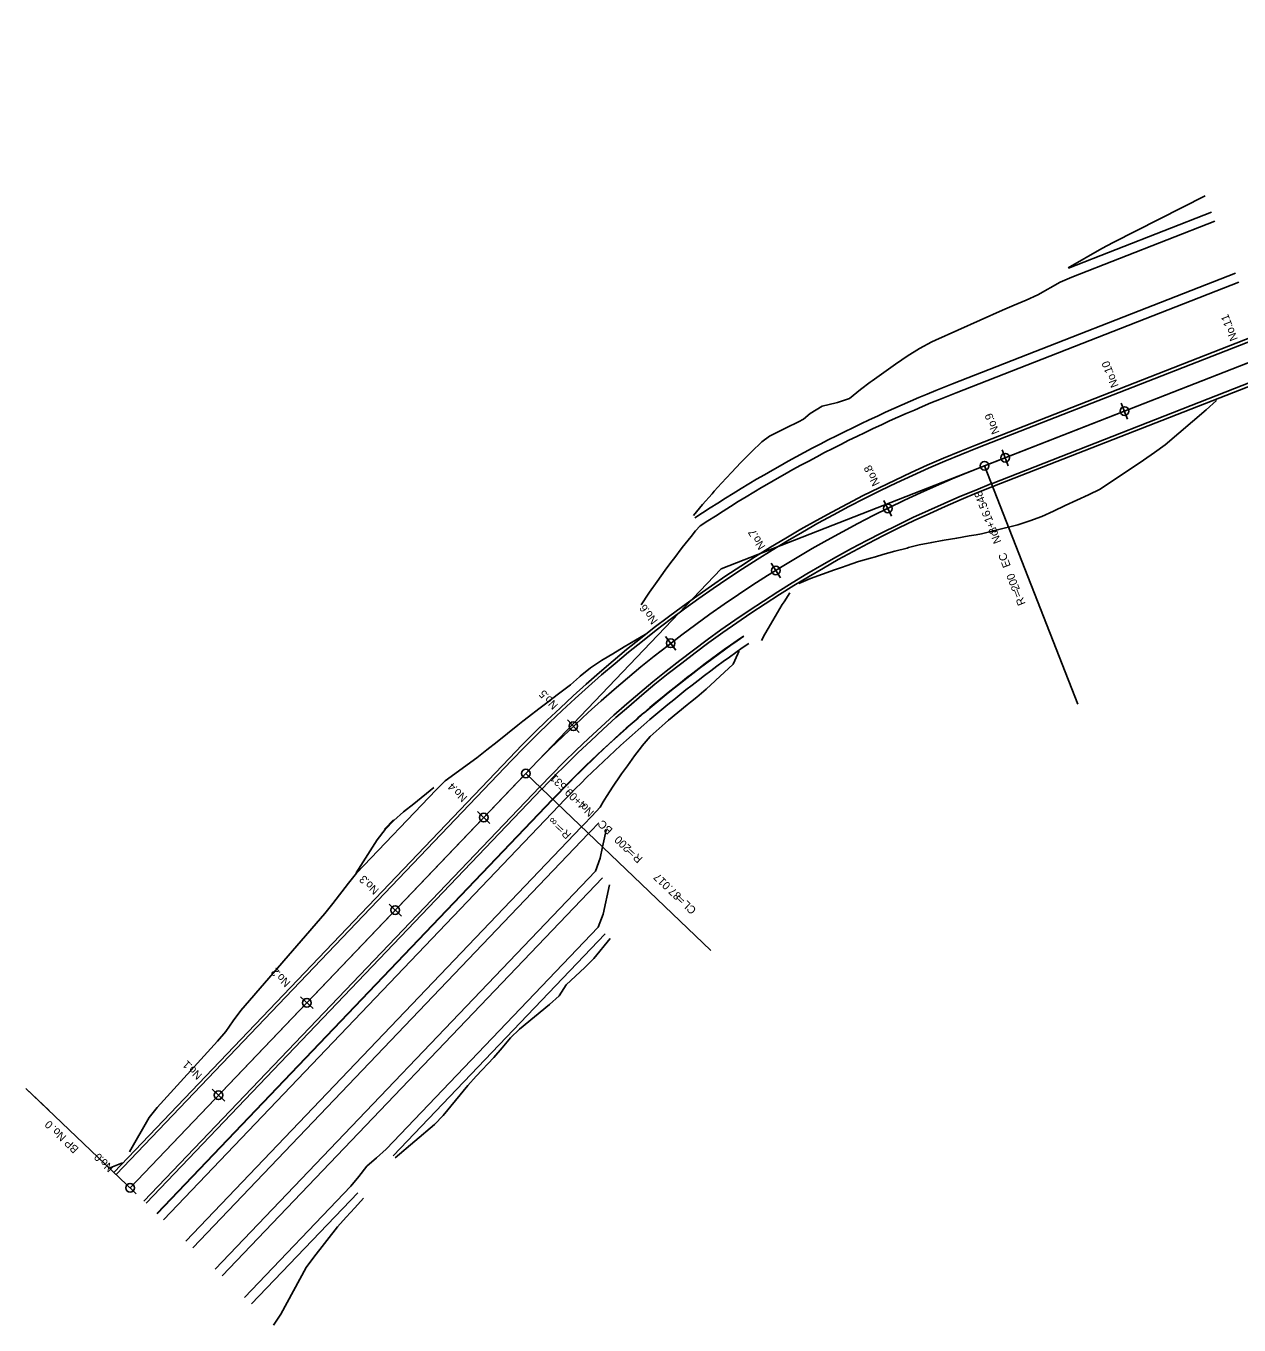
# Model space of a CAD drawing. Extents: x 46571 to 46965, y 10701 to 11034.
# Drawn here: x 46571.1 to 46760.7, y 10701.1 to 10904 of the extents above; entities that cross this region are included whole.
import ezdxf

# ---------------------------------------------------------------- set-up
doc = ezdxf.new("R2010")
doc.units = 0
for name, color, linetype in [('Default', 7, 'Continuous'), ('作業レイヤ1', 7, 'Continuous'), ('地形_土崖 コンクリート、堅固な石積等斜面（地理院地図Vector）', 7, 'Continuous'), ('建物_堅ろう建物_堅ろう建物（外周線）（地理院地図Vector）', 7, 'Continuous'), ('建物_普通建物_普通建物（外周線）（地理院地図Vector）', 7, 'Continuous'), ('河川_通常部（地理院地図Vector）', 7, 'Continuous'), ('現況_地形', 7, 'Continuous'), ('現況_地形_フロー矢印', 7, 'Continuous'), ('現況_地形_単点標高', 7, 'Continuous'), ('等高線等深線_等高線_主曲線通常部（地理院地図Vector）', 7, 'Continuous'), ('道路_通常部_通常部（地理院地図Vector）', 7, 'Continuous')]:
    doc.layers.add(name, color=color, linetype=linetype)

msp = doc.modelspace()

# ---------------------------------------------------------------- linework, layer by layer
at = {"layer": 'Default'}
for p, q in [((46679.76, 10819.21), (46896.47, 10904.04)), ((46720.93, 10835.33), (46842.51, 10882.92)), ((46742.77, 10843.88), (46742.77, 10843.88)), ((46724.14, 10836.59), (46724.14, 10836.59)), ((46720.93, 10835.33), (46720.93, 10835.33)), ((46720.93, 10835.33), (46735.51, 10798.08)), ((46705.79, 10828.67), (46705.79, 10828.67)), ((46587.37, 10722.52), (46679.76, 10819.21)), ((46688.3, 10818.98), (46688.3, 10818.98)), ((46671.86, 10807.59), (46671.86, 10807.59)), ((46656.65, 10794.63), (46656.65, 10794.63)), ((46587.37, 10722.52), (46649.22, 10787.25)), ((46649.22, 10787.25), (46649.22, 10787.25)), ((46649.22, 10787.25), (46678.14, 10759.62)), ((46642.64, 10780.36), (46642.64, 10780.36)), ((46628.82, 10765.9), (46628.82, 10765.9)), ((46615, 10751.44), (46615, 10751.44)), ((46586.88, 10722.98), (46571.1, 10738.06)), ((46571.1, 10738.06), (46574.72, 10734.61)), ((46601.19, 10736.98), (46601.19, 10736.98)), ((46587.37, 10722.52), (46587.37, 10722.52)), ((46587.37, 10722.52), (46587.37, 10722.52))]:
    msp.add_line(p, q, dxfattribs=at)
for centre in [(46742.77, 10843.88), (46720.93, 10835.33), (46724.14, 10836.59), (46705.79, 10828.67), (46688.3, 10818.98), (46671.86, 10807.59), (46656.65, 10794.63), (46649.22, 10787.25), (46642.64, 10780.36), (46628.82, 10765.9), (46615, 10751.44), (46601.19, 10736.98), (46587.37, 10722.52), (46587.37, 10722.52)]:
    msp.add_circle(centre, 0.675, dxfattribs=at)
msp.add_arc((46793.83, 10649.09), 200, 111.3768, 136.3054, dxfattribs=at)
msp.add_arc((46793.83, 10649.09), 200, 111.3768, 136.3054, dxfattribs=at)
at = {"layer": '作業レイヤ1'}
for p, q in [((46720.93, 10835.33), (46842.51, 10882.92)), ((46587.37, 10722.52), (46649.22, 10787.25))]:
    msp.add_line(p, q, dxfattribs=at)
msp.add_arc((46793.83, 10649.09), 200, 111.3768, 136.3054, dxfattribs=at)
at = {"layer": '地形_土崖 コンクリート、堅固な石積等斜面（地理院地図Vector）'}
for p, q in [((46719.83, 10838.12), (46841.42, 10885.71)), ((46722.02, 10832.53), (46843.6, 10880.12)), ((46585.2, 10724.59), (46647.05, 10789.32)), ((46589.54, 10720.44), (46651.39, 10785.18))]:
    msp.add_line(p, q, dxfattribs=at)
for radius in [203, 197]:
    msp.add_arc((46793.83, 10649.09), radius, 111.3768, 136.3054, dxfattribs=at)
at = {"layer": '建物_堅ろう建物_堅ろう建物（外周線）（地理院地図Vector）'}
msp.add_line((46591.57, 10718.51), (46653.41, 10783.24), dxfattribs=at)
msp.add_arc((46793.83, 10649.09), 194.2, 124.7118, 136.3054, dxfattribs=at)
at = {"layer": '建物_普通建物_普通建物（外周線）（地理院地図Vector）'}
for p, q in [((46719.65, 10838.59), (46841.23, 10886.18)), ((46722.2, 10832.07), (46843.78, 10879.66)), ((46584.84, 10724.93), (46646.69, 10789.67)), ((46589.9, 10720.1), (46651.75, 10784.83)), ((46592.59, 10717.53), (46654.44, 10782.26))]:
    msp.add_line(p, q, dxfattribs=at)
for radius, start in [(203.5, 111.3768), (196.5, 111.3768), (192.78, 124.7118)]:
    msp.add_arc((46793.83, 10649.09), radius, start, 136.3054, dxfattribs=at)
at = {"layer": '現況_地形'}
msp.add_line((46591.6, 10718.48), (46653.45, 10783.21), dxfattribs=at)
msp.add_arc((46793.83, 10649.09), 194.15, 124.7118, 136.3054, dxfattribs=at)
at = {"layer": '現況_地形_フロー矢印'}
for p, q in [((46734.03, 10866.19), (46756.38, 10874.94)), ((46715.92, 10848.11), (46760.11, 10865.41)), ((46716.47, 10846.72), (46760.66, 10864.01)), ((46584.13, 10725.61), (46586.2, 10726.4))]:
    msp.add_line(p, q, dxfattribs=at)
for points in [[(46734, 10866.27), (46739.26, 10869.29), (46741.04, 10870.23), (46755.38, 10877.49)], [(46675.41, 10827.55), (46676.85, 10829.26), (46678.32, 10830.95), (46678.68, 10831.35), (46679.82, 10832.62), (46681.35, 10834.27), (46682.83, 10835.83), (46682.9, 10835.9), (46684.48, 10837.51), (46686.09, 10839.09), (46687.31, 10839.93), (46687.94, 10840.26), (46689.89, 10841.24), (46691.86, 10842.19), (46692.62, 10842.6), (46693.64, 10843.5), (46695.52, 10844.63), (46697.7, 10845.15), (46697.95, 10845.21), (46699.79, 10845.86), (46701.53, 10847.27), (46703.03, 10848.38), (46703.33, 10848.6), (46705.15, 10849.9), (46706.99, 10851.19), (46708.01, 10851.9), (46708.84, 10852.46), (46710.73, 10853.65), (46712.7, 10854.69), (46713.25, 10854.95), (46723.72, 10859.62), (46725.55, 10860.42), (46727.4, 10861.18), (46729.22, 10862.02), (46732.73, 10864.03), (46734.58, 10864.79), (46756.93, 10873.54)], [(46691.87, 10816.95), (46693.7, 10817.71), (46695.57, 10818.4), (46697.44, 10819.07), (46698.71, 10819.51), (46699.31, 10819.72), (46701.19, 10820.36), (46703.1, 10820.91), (46703.86, 10821.12), (46705.01, 10821.44), (46706.91, 10821.97), (46708.82, 10822.48), (46709.04, 10822.54), (46710.72, 10822.99), (46712.67, 10823.36), (46714.3, 10823.65), (46714.62, 10823.71), (46716.57, 10824.04), (46718.51, 10824.36), (46719.59, 10824.54), (46720.43, 10824.71), (46722.3, 10825.17), (46724.17, 10825.62), (46724.68, 10825.75), (46726.1, 10826.09), (46728, 10826.74), (46729.89, 10827.4), (46731.71, 10828.22), (46733.51, 10829.12), (46735.32, 10829.98), (46737.14, 10830.81), (46738.96, 10831.66), (46745.76, 10836.22), (46747.45, 10837.38), (46749.13, 10838.6), (46755.57, 10844.09), (46757.16, 10845.51)], [(46667.24, 10813.6), (46668.47, 10815.42), (46668.57, 10815.57), (46669.73, 10817.23), (46671.01, 10819.01), (46672.06, 10820.43), (46672.33, 10820.79), (46673.67, 10822.54), (46675.04, 10824.28), (46675.76, 10825.17), (46676.49, 10825.93)]]:
    msp.add_lwpolyline(points, dxfattribs=at)
for radius in [213.73, 212.23]:
    msp.add_arc((46793.83, 10649.09), radius, 111.3768, 123.5659, dxfattribs=at)
at = {"layer": '現況_地形_単点標高'}
for p, q in [((46627.15, 10778.56), (46628.54, 10780)), ((46601.78, 10708.75), (46661.19, 10770.93)), ((46628.47, 10727.5), (46661.63, 10762.21)), ((46606.37, 10704.37), (46622.95, 10721.72))]:
    msp.add_line(p, q, dxfattribs=at)
for points in [[(46686.07, 10808.02), (46686.6, 10809.01), (46687.11, 10809.92), (46688.19, 10811.8), (46689.31, 10813.65), (46689.59, 10814.09), (46690.48, 10815.47)], [(46587.27, 10728.15), (46590.37, 10733.48), (46591.6, 10735.07), (46601.03, 10745.43), (46602.33, 10746.95), (46603.51, 10748.59), (46604.7, 10750.22), (46617.79, 10765.38), (46619.04, 10766.95), (46621.51, 10770.12), (46622.78, 10771.67), (46635.22, 10784.68), (46636.61, 10786.11), (46641.55, 10789.7), (46643.13, 10790.95), (46644.72, 10792.22), (46646.34, 10793.52), (46647.98, 10794.81), (46648.77, 10795.43), (46649.62, 10796.08), (46651.27, 10797.34), (46652.92, 10798.58), (46653.26, 10798.84), (46654.56, 10799.84), (46656.18, 10801.11), (46657.6, 10802.36), (46657.72, 10802.46), (46659.31, 10803.75), (46661.04, 10804.88), (46662.18, 10805.58), (46662.81, 10805.96), (46664.58, 10807.03), (46666.35, 10808.08), (46666.99, 10808.46), (46668.12, 10809.12)], [(46596.1, 10714.18), (46657.95, 10778.91), (46658.25, 10779.23), (46659.56, 10780.58), (46660.82, 10781.98), (46661.29, 10782.8), (46661.81, 10783.65), (46662.88, 10785.26), (46663.97, 10786.86), (46664.19, 10787.18), (46665.09, 10788.44), (46666.23, 10790), (46667.31, 10791.43), (46667.4, 10791.55), (46668.64, 10793.03), (46670.06, 10794.3), (46670.98, 10795.11), (46671.5, 10795.56), (46672.96, 10796.79), (46674.44, 10797.99), (46674.98, 10798.42), (46675.93, 10799.17), (46677.39, 10800.41), (46678.79, 10801.72), (46678.91, 10801.83), (46680.22, 10803.01), (46681.62, 10804.34), (46682.35, 10805.95), (46682.54, 10806.35)], [(46622.7, 10771.74), (46625.99, 10776.9), (46627.23, 10778.49), (46628.61, 10779.93), (46630.13, 10781.25), (46631.72, 10782.49), (46634.84, 10785.04)], [(46597.19, 10713.14), (46659.03, 10777.87), (46659.34, 10778.19), (46660.63, 10779.53)], [(46600.69, 10709.79), (46660.1, 10771.97), (46660.84, 10774.03), (46661.23, 10775.78), (46661.33, 10776.28), (46661.79, 10778.39)], [(46605.28, 10705.4), (46621.86, 10722.76), (46623.15, 10724.3), (46624.36, 10725.9), (46625.9, 10727.2), (46627.39, 10728.54), (46660.55, 10763.25), (46661.32, 10765.27), (46662.32, 10769.85)], [(46628.78, 10727.21), (46634.94, 10732.39), (46636.32, 10733.84), (46640.15, 10738.48), (46641.47, 10739.98), (46644.23, 10742.88), (46645.53, 10744.4), (46646.82, 10745.94), (46648.26, 10747.33), (46652.91, 10751.18), (46654.41, 10752.51), (46655.53, 10754.21), (46658.47, 10756.94), (46659.87, 10758.36), (46662.42, 10761.46)], [(46609.81, 10701.08), (46610.95, 10702.76), (46614.9, 10710.05), (46616.09, 10711.67), (46619.81, 10716.42), (46621.12, 10717.93), (46622.52, 10719.37), (46623.83, 10720.88)]]:
    msp.add_lwpolyline(points, dxfattribs=at)
at = {"layer": '等高線等深線_等高線_主曲線通常部（地理院地図Vector）'}
for p, q in [((46720.93, 10835.33), (46842.51, 10882.92)), ((46587.37, 10722.52), (46649.22, 10787.25))]:
    msp.add_line(p, q, dxfattribs=at)
msp.add_arc((46793.83, 10649.09), 200, 111.3768, 136.3054, dxfattribs=at)
at = {"layer": '道路_通常部_通常部（地理院地図Vector）'}
for p, q in [((46742.27, 10845.13), (46743.26, 10842.62)), ((46723.65, 10837.84), (46724.63, 10835.33)), ((46705.19, 10829.88), (46706.38, 10827.45)), ((46687.58, 10820.13), (46689.01, 10817.83)), ((46671.04, 10808.66), (46672.69, 10806.53)), ((46655.72, 10795.61), (46657.57, 10793.64)), ((46641.66, 10781.29), (46643.61, 10779.43)), ((46627.84, 10766.83), (46629.8, 10764.97)), ((46614.03, 10752.37), (46615.98, 10750.51)), ((46600.21, 10737.91), (46602.16, 10736.04)), ((46586.4, 10723.45), (46588.35, 10721.58))]:
    msp.add_line(p, q, dxfattribs=at)

# ---------------------------------------------------------------- texts
at = {"layer": 'Default'}
for s, rotation, p in [('8+16.548', 111.3768, (46722.96, 10824.99)), ('EC\u3000No.', 111.3768, (46725.03, 10819.7)), ('200', 111.3768, (46726.46, 10816.05)), ('R＝', 111.3768, (46727.35, 10813.78)), ('4+09.531', 136.3054, (46658.79, 10782.43)), ('BC\u3000No.', 136.3054, (46662.9, 10778.5)), ('R＝∞', 136.3054, (46656.42, 10777.78)), ('200', 136.3054, (46665.82, 10775.71)), ('R＝', 136.3054, (46667.58, 10774.03)), ('87.017', 136.3054, (46673.62, 10768.26)), ('CL＝', 136.3054, (46675.97, 10766.02)), ('0', 136.3054, (46575.44, 10732.51)), ('BP No.', 136.3054, (46579.44, 10728.69))]:
    msp.add_text(s, height=1.25, rotation=rotation, dxfattribs=at).set_placement(p)
at = {"layer": '河川_通常部（地理院地図Vector）'}
for s, rotation, p in [('11', 111.3768, (46759.63, 10857.39)), ('No.', 111.3768, (46760.51, 10855.12)), ('10', 111.3768, (46741, 10850.1)), ('No.', 111.3768, (46741.89, 10847.83)), ('9', 111.3768, (46722.38, 10842.81)), ('No.', 111.3768, (46723.27, 10840.54)), ('8', 116.1174, (46703.51, 10834.72)), ('No.', 116.1174, (46704.59, 10832.53)), ('7', 121.847, (46685.43, 10824.78)), ('No.', 121.847, (46686.72, 10822.71)), ('6', 127.5766, (46668.43, 10813.08)), ('No.', 127.5766, (46669.92, 10811.15)), ('5', 133.3061, (46652.69, 10799.74)), ('No.', 133.3061, (46654.36, 10797.97)), ('4', 136.3054, (46638.42, 10785.26)), ('No.', 136.3054, (46640.18, 10783.57)), ('3', 136.3054, (46624.6, 10770.8)), ('No.', 136.3054, (46626.36, 10769.11)), ('2', 136.3054, (46610.78, 10756.34)), ('No.', 136.3054, (46612.54, 10754.65)), ('1', 136.3054, (46596.97, 10741.88)), ('No.', 136.3054, (46598.73, 10740.19)), ('0', 136.3054, (46583.15, 10727.41)), ('No.', 136.3054, (46584.91, 10725.73))]:
    msp.add_text(s, height=1.25, rotation=rotation, dxfattribs=at).set_placement(p)

doc.saveas('drawing.dxf')
